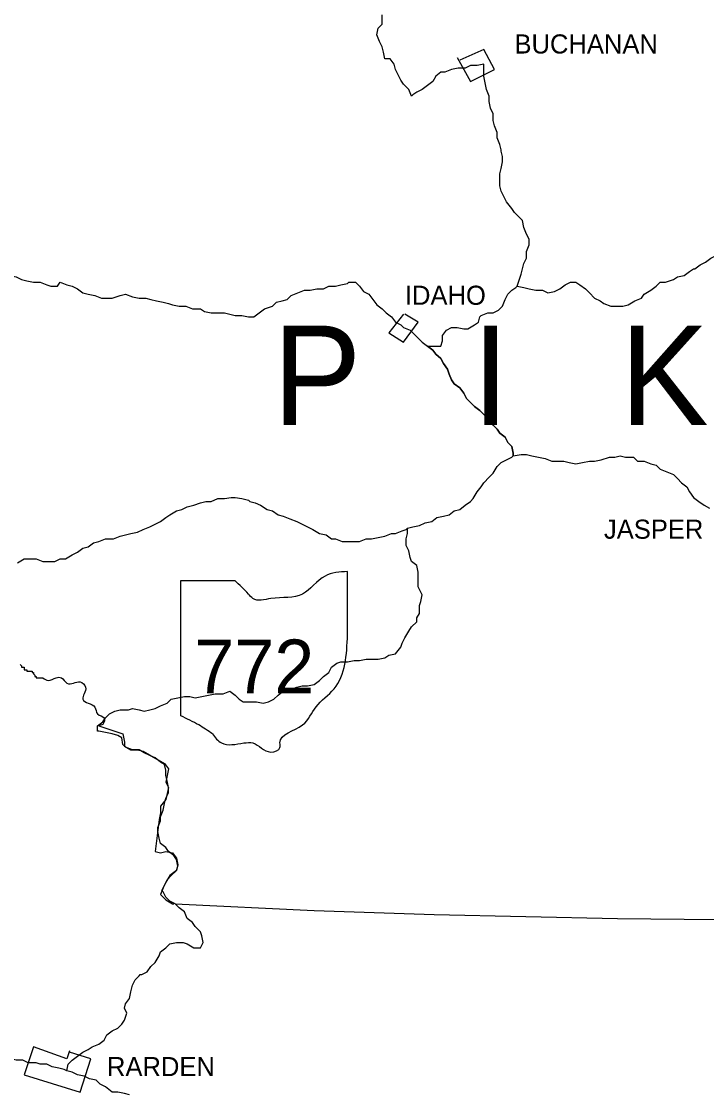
# Model space of a CAD drawing. Extents: x 0 to 34, y 0 to 22.
# Drawn here: x 5.139 to 5.838, y 17.195 to 18.289 of the extents above; entities that cross this region are included whole.
import ezdxf

# ---------------------------------------------------------------- set-up
doc = ezdxf.new("R2010")
doc.units = 0
doc.layers.add('Default', color=7, linetype='Continuous')
doc.layers.add('TR_Turning_Path1', color=7, linetype='Continuous')

msp = doc.modelspace()

# ---------------------------------------------------------------- linework, layer by layer
at = {"layer": 'Default'}
msp.add_line((5.2224, 17.5717), (5.2183, 17.5703), dxfattribs=at)
for points in [[(5.5373, 18.2125), (5.5346, 18.2193), (5.5291, 18.2247), (5.5264, 18.2288), (5.5237, 18.2343), (5.521, 18.2397), (5.5196, 18.2452), (5.5155, 18.2506), (5.51, 18.2506), (5.5087, 18.2575), (5.5073, 18.2629), (5.5046, 18.2684), (5.5019, 18.2752), (5.5032, 18.282), (5.5073, 18.2861), (5.5073, 18.2929), (5.5073, 18.2956)], [(5.5837, 18.252), (5.5973, 18.2275), (5.6218, 18.2397), (5.6109, 18.2602), (5.5864, 18.2493)], [(5.6109, 18.2452), (5.6041, 18.2438), (5.5973, 18.2438), (5.5919, 18.2411), (5.585, 18.2411), (5.5782, 18.2397), (5.5714, 18.237), (5.5673, 18.237), (5.5619, 18.2329), (5.5591, 18.2275), (5.5537, 18.2234), (5.5482, 18.2193), (5.5428, 18.2166), (5.5387, 18.2138), (5.5373, 18.2125)], [(5.6287, 18.1579), (5.6273, 18.1634), (5.6246, 18.1702), (5.6246, 18.1757), (5.6218, 18.1825), (5.6205, 18.1879), (5.6205, 18.1947), (5.6178, 18.2002), (5.6164, 18.207), (5.6164, 18.2125), (5.6137, 18.2193), (5.6123, 18.2261), (5.6109, 18.2329), (5.6109, 18.237), (5.6109, 18.2438), (5.6109, 18.2452)], [(5.645, 18.0189), (5.6464, 18.0229), (5.6491, 18.0311), (5.6505, 18.0366), (5.6518, 18.042), (5.6546, 18.0475), (5.6546, 18.0543), (5.6573, 18.0611), (5.6573, 18.0666), (5.6546, 18.072), (5.6518, 18.0788), (5.6505, 18.0857), (5.6464, 18.0898), (5.6423, 18.0938), (5.6396, 18.0979), (5.6341, 18.1048), (5.6314, 18.1102), (5.6287, 18.1157), (5.6273, 18.1211), (5.6273, 18.1266), (5.6273, 18.1334), (5.6287, 18.1388), (5.63, 18.1457), (5.63, 18.1511), (5.6287, 18.1566), (5.6287, 18.1566), (5.6287, 18.1579)], [(5.8264, 18.0366), (5.8318, 18.0407), (5.8373, 18.0434), (5.8427, 18.0475), (5.8482, 18.0502), (5.8536, 18.0516), (5.8604, 18.0516), (5.8659, 18.0516), (5.8714, 18.0489), (5.8782, 18.0475), (5.8836, 18.0489), (5.8864, 18.0502)], [(5.056, 17.9957), (5.0628, 17.9957), (5.0669, 17.9998), (5.071, 18.0039), (5.0778, 18.0066), (5.0819, 18.012), (5.0874, 18.0161), (5.0928, 18.0202), (5.0969, 18.0243), (5.101, 18.0284), (5.1078, 18.0311), (5.1133, 18.0325), (5.1201, 18.0311), (5.1269, 18.0298), (5.1337, 18.0284), (5.1392, 18.0257), (5.1447, 18.0243), (5.1515, 18.0229), (5.1583, 18.0229), (5.1651, 18.0202), (5.1692, 18.0189), (5.176, 18.0189), (5.176, 18.0189)], [(5.645, 18.0189), (5.6518, 18.0175), (5.6573, 18.0161), (5.6641, 18.0148), (5.6709, 18.0148), (5.6764, 18.012), (5.6832, 18.0134), (5.6887, 18.0161), (5.6941, 18.0202), (5.6996, 18.0229), (5.705, 18.0229), (5.7091, 18.0202), (5.7146, 18.0161), (5.7187, 18.012), (5.7241, 18.0066), (5.7296, 18.0039), (5.7336, 18.0011), (5.7405, 17.9984), (5.7473, 17.9984), (5.7527, 17.9984), (5.7582, 17.9998), (5.765, 18.0039), (5.7718, 18.0066), (5.7746, 18.0107), (5.7814, 18.0148), (5.7868, 18.0189), (5.7909, 18.0229), (5.7964, 18.0229), (5.8045, 18.0257), (5.8086, 18.0284), (5.8155, 18.0298), (5.8209, 18.0339), (5.825, 18.0366), (5.8264, 18.0366), (5.8264, 18.0366)], [(5.176, 18.0189), (5.1787, 18.0229), (5.1856, 18.0202), (5.191, 18.0189), (5.1965, 18.0161), (5.2019, 18.012), (5.2074, 18.0107), (5.2142, 18.0093), (5.221, 18.0066), (5.2265, 18.0066), (5.2319, 18.0066), (5.2401, 18.0093), (5.2455, 18.0107), (5.2524, 18.0079), (5.2592, 18.0066), (5.266, 18.0066), (5.2714, 18.0052), (5.2769, 18.0039), (5.2837, 18.0025), (5.2892, 18.0011), (5.2933, 17.9998), (5.2933, 17.9998)], [(5.2933, 17.9998), (5.3001, 17.9984), (5.3069, 17.9984), (5.3137, 17.9957), (5.3219, 17.9957), (5.326, 17.993), (5.3328, 17.9916), (5.3396, 17.9916), (5.3464, 17.9916), (5.3519, 17.9902), (5.3573, 17.9889), (5.3642, 17.9889), (5.371, 17.9875), (5.3764, 17.9875), (5.3819, 17.9916), (5.3873, 17.9957), (5.3955, 17.9984), (5.3996, 18.0025), (5.4051, 18.0039), (5.4105, 18.0052), (5.4146, 18.0093), (5.4214, 18.012), (5.4282, 18.0148), (5.4337, 18.0148), (5.4405, 18.0161), (5.4473, 18.0161), (5.4528, 18.0189), (5.4596, 18.0189), (5.4651, 18.0202), (5.4719, 18.0216), (5.4732, 18.0229)], [(5.4732, 18.0229), (5.4801, 18.0229), (5.4841, 18.0189), (5.4882, 18.0134), (5.4937, 18.0107), (5.4978, 18.0052), (5.5019, 17.9998), (5.5073, 17.9957), (5.5114, 17.9916), (5.5169, 17.9875), (5.521, 17.982), (5.5264, 17.9793), (5.5291, 17.9766), (5.536, 17.9739), (5.5387, 17.9711), (5.5441, 17.9657), (5.5482, 17.9616), (5.5537, 17.9575), (5.5537, 17.9575), (5.5537, 17.9575)], [(5.6082, 17.9889), (5.615, 17.9916), (5.6205, 17.9916), (5.6259, 17.9943), (5.63, 17.9984), (5.6328, 18.0052), (5.6355, 18.0107), (5.6396, 18.0148), (5.6437, 18.0175), (5.645, 18.0189)], [(5.5291, 17.9902), (5.5141, 17.9711), (5.5291, 17.9616), (5.5441, 17.982), (5.5305, 17.9902)], [(5.5537, 17.9575), (5.5605, 17.9575), (5.5673, 17.9575), (5.5687, 17.963), (5.5687, 17.9684), (5.5728, 17.9739), (5.5782, 17.9766), (5.5837, 17.9766), (5.5905, 17.9752), (5.5946, 17.9752), (5.6014, 17.9793), (5.6055, 17.982), (5.6069, 17.9875), (5.6069, 17.9875), (5.6082, 17.9889)], [(5.6409, 17.8457), (5.6409, 17.8471), (5.6409, 17.8484), (5.6396, 17.8552), (5.6355, 17.8593), (5.6328, 17.8648), (5.6273, 17.8689), (5.6246, 17.873), (5.6205, 17.8771), (5.6164, 17.8825), (5.6109, 17.888), (5.6069, 17.8921), (5.6014, 17.8961), (5.5973, 17.9002), (5.5932, 17.9043), (5.5905, 17.9098), (5.5864, 17.9152), (5.5809, 17.9193), (5.5782, 17.9234), (5.5755, 17.9289), (5.5741, 17.9343), (5.57, 17.9398), (5.5673, 17.9452), (5.5619, 17.9493), (5.5591, 17.9534), (5.5537, 17.9575)], [(5.5537, 17.9575), (5.5591, 17.9534), (5.5619, 17.9493), (5.5673, 17.9452), (5.57, 17.9398), (5.5741, 17.9343), (5.5755, 17.9289), (5.5782, 17.9234), (5.5809, 17.9193), (5.5864, 17.9152), (5.5905, 17.9098), (5.5932, 17.9043), (5.5973, 17.9002), (5.6014, 17.8961), (5.6069, 17.8921), (5.6109, 17.888), (5.6164, 17.8825), (5.6205, 17.8771), (5.6246, 17.873), (5.6273, 17.8689), (5.6328, 17.8648), (5.6355, 17.8593), (5.6396, 17.8552), (5.6409, 17.8484), (5.6409, 17.8471), (5.6409, 17.8457)], [(5.5332, 17.7721), (5.5387, 17.7734), (5.5455, 17.7748), (5.551, 17.7775), (5.5578, 17.7789), (5.5632, 17.783), (5.57, 17.7843), (5.5755, 17.7857), (5.5809, 17.7898), (5.5864, 17.7912), (5.5919, 17.7953), (5.5973, 17.7993), (5.6, 17.8021), (5.6041, 17.8089), (5.6082, 17.8143), (5.6109, 17.8184), (5.6164, 17.8239), (5.6205, 17.828), (5.6246, 17.8348), (5.6287, 17.8389), (5.6341, 17.8416), (5.6396, 17.8443), (5.6409, 17.8457), (5.6409, 17.8457)], [(5.5332, 17.7721), (5.5387, 17.7734), (5.5455, 17.7748), (5.551, 17.7775), (5.5578, 17.7789), (5.5632, 17.783), (5.57, 17.7843), (5.5755, 17.7857), (5.5809, 17.7898), (5.5864, 17.7912), (5.5919, 17.7953), (5.5973, 17.7993), (5.6, 17.8021), (5.6041, 17.8089), (5.6082, 17.8143), (5.6109, 17.8184), (5.6164, 17.8239), (5.6205, 17.828), (5.6246, 17.8348), (5.6287, 17.8389), (5.6341, 17.8416), (5.6396, 17.8443), (5.6409, 17.8457), (5.6409, 17.8457)], [(5.6409, 17.8457), (5.6491, 17.8471), (5.6546, 17.8471), (5.66, 17.8457), (5.6668, 17.8443), (5.6737, 17.843), (5.6805, 17.8402), (5.6859, 17.8402), (5.6927, 17.8402), (5.6982, 17.8389), (5.705, 17.8375), (5.7118, 17.8389), (5.7187, 17.8402), (5.7241, 17.8402), (5.7309, 17.8416), (5.7391, 17.8443), (5.7446, 17.8443), (5.75, 17.8457), (5.7555, 17.8443), (5.7636, 17.8443), (5.7677, 17.8402), (5.7746, 17.8402), (5.7814, 17.8375), (5.7868, 17.8362), (5.7909, 17.8321), (5.7977, 17.8293), (5.8045, 17.8266), (5.8086, 17.8225), (5.8127, 17.8184), (5.8182, 17.8143), (5.8209, 17.8089), (5.825, 17.8034), (5.8305, 17.7993), (5.8359, 17.7953), (5.8414, 17.7925)], [(5.6409, 17.8457), (5.6491, 17.8471), (5.6546, 17.8471), (5.66, 17.8457), (5.6668, 17.8443), (5.6737, 17.843), (5.6805, 17.8402), (5.6859, 17.8402), (5.6927, 17.8402), (5.6982, 17.8389), (5.705, 17.8375), (5.7118, 17.8389), (5.7187, 17.8402), (5.7241, 17.8402), (5.7309, 17.8416), (5.7391, 17.8443), (5.7446, 17.8443), (5.75, 17.8457), (5.7555, 17.8443), (5.7636, 17.8443), (5.7677, 17.8402), (5.7746, 17.8402), (5.7814, 17.8375), (5.7868, 17.8362), (5.7909, 17.8321), (5.7977, 17.8293), (5.8045, 17.8266), (5.8086, 17.8225), (5.8127, 17.8184), (5.8182, 17.8143), (5.8209, 17.8089), (5.825, 17.8034), (5.8305, 17.7993), (5.8359, 17.7953), (5.8414, 17.7925)], [(5.2265, 17.7612), (5.2333, 17.7612), (5.2401, 17.7639), (5.2455, 17.7653), (5.251, 17.7666), (5.2578, 17.768), (5.2633, 17.7707), (5.2701, 17.7734), (5.2755, 17.7762), (5.281, 17.7789), (5.2864, 17.783), (5.2905, 17.7857), (5.2974, 17.7898), (5.3028, 17.7912), (5.3083, 17.7939), (5.3151, 17.7953), (5.3219, 17.798), (5.3273, 17.7993), (5.3328, 17.7993), (5.3396, 17.8021), (5.3464, 17.8021), (5.3533, 17.8034), (5.3573, 17.8034), (5.3642, 17.8021), (5.371, 17.8007), (5.3723, 17.7993), (5.3723, 17.7993)], [(5.3723, 17.7993), (5.3778, 17.798), (5.3832, 17.7953), (5.3901, 17.7912), (5.3955, 17.7898), (5.401, 17.7857), (5.4064, 17.7843), (5.4132, 17.7816), (5.4201, 17.7789), (5.4255, 17.7762), (5.431, 17.7734), (5.4364, 17.7707), (5.4432, 17.7666), (5.4501, 17.7653), (5.4555, 17.7612), (5.4596, 17.7612), (5.4664, 17.7584), (5.4719, 17.7584), (5.4787, 17.7584), (5.4841, 17.7584), (5.491, 17.7612), (5.4964, 17.7612), (5.5032, 17.7625), (5.51, 17.7639), (5.5169, 17.7666), (5.521, 17.7666), (5.5278, 17.7694), (5.5319, 17.7707), (5.5332, 17.7721)], [(5.5428, 17.6807), (5.5455, 17.6848), (5.5455, 17.693), (5.5469, 17.6971), (5.5482, 17.7039), (5.5455, 17.7094), (5.5441, 17.7121), (5.5441, 17.7203), (5.5441, 17.7271), (5.5428, 17.7339), (5.5373, 17.738), (5.536, 17.7421), (5.5346, 17.7489), (5.5319, 17.7544), (5.5319, 17.7612), (5.5332, 17.7666), (5.5332, 17.7707), (5.5332, 17.7721)], [(5.1351, 17.7366), (5.1419, 17.7407), (5.1474, 17.7407), (5.1542, 17.7407), (5.161, 17.738), (5.1665, 17.738), (5.1733, 17.738), (5.1787, 17.7407), (5.1842, 17.7407), (5.191, 17.7448), (5.1965, 17.7475), (5.2019, 17.7516), (5.2074, 17.753), (5.2128, 17.7571), (5.2183, 17.7584), (5.2251, 17.7612), (5.2265, 17.7612), (5.2265, 17.7612)], [(5.472, 17.6633), (5.472, 17.7278)], [(5.3018, 17.5805), (5.3018, 17.7186), (5.357, 17.7186)], [(5.4841, 17.6371), (5.491, 17.6385), (5.4964, 17.6385), (5.5032, 17.6385), (5.51, 17.6398), (5.5141, 17.6426), (5.521, 17.6439), (5.5264, 17.6507), (5.5278, 17.6548), (5.5305, 17.6603), (5.5346, 17.6671), (5.5373, 17.6712), (5.5428, 17.6766), (5.5428, 17.6794), (5.5428, 17.6807)], [(5.1378, 17.633), (5.1392, 17.6316), (5.1392, 17.6316), (5.1392, 17.6316), (5.1392, 17.6316), (5.1392, 17.6316), (5.1392, 17.6316), (5.1392, 17.6303), (5.1392, 17.6303), (5.1392, 17.6303), (5.1392, 17.6303), (5.1406, 17.6303), (5.1406, 17.6303), (5.1419, 17.6303), (5.1419, 17.6303), (5.1419, 17.6303), (5.1419, 17.6303), (5.1419, 17.6303), (5.1419, 17.6289), (5.1419, 17.6289), (5.1419, 17.6276), (5.1433, 17.6276), (5.1433, 17.6276), (5.1433, 17.6276), (5.1433, 17.6276), (5.1447, 17.6276), (5.1447, 17.6276), (5.1447, 17.6262), (5.1447, 17.6262), (5.146, 17.6262), (5.146, 17.6262), (5.146, 17.6262), (5.146, 17.6262), (5.1474, 17.6262), (5.1474, 17.6262), (5.1487, 17.6262), (5.1487, 17.6262), (5.1487, 17.6262), (5.1487, 17.6262), (5.1501, 17.6262), (5.1501, 17.6262), (5.1501, 17.6262), (5.1501, 17.6262), (5.1501, 17.6262), (5.1501, 17.6248), (5.1501, 17.6248), (5.1515, 17.6248), (5.1515, 17.6248), (5.1515, 17.6235), (5.1515, 17.6235), (5.1515, 17.6235), (5.1515, 17.6235), (5.1515, 17.6235), (5.1515, 17.6235), (5.1515, 17.6235), (5.1515, 17.6235), (5.1528, 17.6221), (5.1528, 17.6221), (5.1528, 17.6221), (5.1528, 17.6221), (5.1528, 17.6221), (5.1528, 17.6207), (5.1542, 17.6207), (5.1542, 17.6194), (5.1556, 17.6194), (5.1556, 17.6194), (5.1556, 17.6194), (5.1556, 17.6194), (5.1556, 17.6194), (5.1556, 17.6194), (5.1556, 17.6194), (5.1556, 17.6194), (5.1569, 17.6194), (5.1583, 17.6194), (5.1583, 17.6194)], [(5.3451, 17.603), (5.3519, 17.6057), (5.3573, 17.6017), (5.3614, 17.5976), (5.3655, 17.5948), (5.3723, 17.5948), (5.3792, 17.5948), (5.386, 17.5935), (5.3914, 17.5948), (5.3969, 17.5976), (5.401, 17.6017), (5.4064, 17.6057), (5.4132, 17.6071), (5.4201, 17.6098), (5.4255, 17.6112), (5.431, 17.6112), (5.4378, 17.6126), (5.4432, 17.6166), (5.4473, 17.6207), (5.4528, 17.6248), (5.4555, 17.6303), (5.461, 17.6344), (5.4651, 17.6357), (5.4719, 17.6357), (5.4787, 17.6371), (5.4828, 17.6371), (5.4841, 17.6371)], [(5.1583, 17.6194), (5.1583, 17.6194), (5.1583, 17.6194), (5.1583, 17.6194), (5.1583, 17.6194), (5.1583, 17.6194), (5.1596, 17.6194), (5.1596, 17.6194), (5.1596, 17.6194), (5.1596, 17.6194), (5.1596, 17.6194), (5.1596, 17.6194), (5.1596, 17.6194), (5.161, 17.6194), (5.161, 17.6194), (5.161, 17.6194), (5.161, 17.6194)], [(5.2251, 17.5785), (5.2292, 17.5826), (5.2346, 17.5853), (5.2401, 17.5867), (5.2483, 17.5867), (5.2524, 17.588), (5.2592, 17.5867), (5.2646, 17.5853), (5.2701, 17.5867), (5.2755, 17.588), (5.281, 17.5907), (5.2878, 17.5935), (5.2919, 17.5976), (5.2987, 17.5989), (5.3055, 17.6003), (5.311, 17.6003), (5.3164, 17.5989), (5.3233, 17.6003), (5.3301, 17.6017), (5.3369, 17.603), (5.3437, 17.603), (5.3451, 17.603)], [(5.2169, 17.5648), (5.2169, 17.5703), (5.2224, 17.5744), (5.2251, 17.5785)], [(5.281, 17.4776), (5.2837, 17.4844), (5.2851, 17.4912), (5.2864, 17.4967), (5.2892, 17.5021), (5.2892, 17.5076), (5.2878, 17.5144), (5.2864, 17.5198), (5.2864, 17.5253), (5.2851, 17.5308), (5.281, 17.5335), (5.2755, 17.5376), (5.2701, 17.5403), (5.2646, 17.543), (5.2592, 17.5458), (5.2524, 17.5458), (5.2455, 17.5485), (5.2428, 17.5512), (5.2415, 17.558), (5.2374, 17.5607), (5.2319, 17.5621), (5.2251, 17.5635), (5.2183, 17.5648), (5.2169, 17.5648), (5.2169, 17.5648)], [(5.2183, 17.5703), (5.2428, 17.5621), (5.2442, 17.5539), (5.2442, 17.5498), (5.251, 17.5458), (5.2578, 17.5458), (5.2633, 17.5444), (5.2851, 17.5321), (5.2892, 17.5267), (5.2878, 17.5198), (5.2864, 17.513), (5.2892, 17.5076), (5.2864, 17.4953), (5.281, 17.4885), (5.281, 17.4817), (5.2796, 17.4749), (5.2755, 17.4421), (5.281, 17.4408), (5.2864, 17.4421), (5.2933, 17.4408), (5.2974, 17.4353), (5.2987, 17.4285), (5.2974, 17.423), (5.2905, 17.4176), (5.2864, 17.4108), (5.2837, 17.4053), (5.281, 17.3985), (5.2864, 17.393), (5.2933, 17.389), (5.2946, 17.389)], [(5.2824, 17.4026), (5.2851, 17.408), (5.2878, 17.4135), (5.2919, 17.4176), (5.2974, 17.423), (5.2987, 17.4271), (5.2974, 17.4339), (5.2946, 17.438), (5.2892, 17.4421), (5.2864, 17.4462), (5.281, 17.4503), (5.2796, 17.4558), (5.2783, 17.4626), (5.2783, 17.4667), (5.281, 17.4735), (5.281, 17.4776), (5.281, 17.4776)], [(5.2619, 17.3167), (5.2674, 17.3194), (5.2714, 17.3249), (5.2755, 17.329), (5.2796, 17.3358), (5.281, 17.3399), (5.2864, 17.344), (5.2905, 17.3481), (5.2974, 17.3494), (5.3042, 17.3494), (5.3083, 17.3481), (5.3151, 17.344), (5.3219, 17.344), (5.3246, 17.3494), (5.3233, 17.3562), (5.3219, 17.3603), (5.3164, 17.3658), (5.3137, 17.3699), (5.3083, 17.374), (5.3055, 17.3808), (5.3001, 17.3849), (5.296, 17.389), (5.2905, 17.3917), (5.2864, 17.3958), (5.2837, 17.4012), (5.2837, 17.4012), (5.2824, 17.4026)], [(5.296, 17.389), (5.4378, 17.3821), (5.5605, 17.378), (5.7473, 17.374), (5.8836, 17.3726), (5.9518, 17.3699), (6.1413, 17.3617), (6.4194, 17.3467), (6.5299, 17.3399), (6.6894, 17.329), (6.7235, 17.3262)], [(5.1856, 17.2185), (5.1869, 17.2253), (5.191, 17.2294), (5.1965, 17.2335), (5.2019, 17.2376), (5.2074, 17.2403), (5.2115, 17.2431), (5.2183, 17.2458), (5.2237, 17.2499), (5.2265, 17.2553), (5.2319, 17.2594), (5.2374, 17.2622), (5.2415, 17.2662), (5.2442, 17.2703), (5.2469, 17.2772), (5.2442, 17.2826), (5.2455, 17.2867), (5.2496, 17.2922), (5.251, 17.299), (5.2524, 17.3058), (5.2551, 17.3112), (5.2592, 17.3153), (5.2605, 17.3167), (5.2619, 17.3167)], [(5.1856, 17.2185), (5.1828, 17.2199), (5.1774, 17.2213), (5.1706, 17.2226), (5.1651, 17.2253), (5.1583, 17.2253), (5.1542, 17.2267), (5.146, 17.2267), (5.1406, 17.2294), (5.1337, 17.2294), (5.1283, 17.2308), (5.1201, 17.2335), (5.116, 17.2363), (5.1119, 17.2403), (5.1065, 17.2431), (5.1024, 17.2499), (5.0969, 17.2526), (5.0901, 17.254)], [(5.1883, 17.239), (5.1856, 17.2308), (5.1515, 17.2431), (5.1419, 17.2144), (5.1992, 17.1967), (5.2101, 17.2308), (5.1883, 17.2376)], [(5.2496, 17.194), (5.2442, 17.1954), (5.2374, 17.1967), (5.2319, 17.1967), (5.2251, 17.2022), (5.2196, 17.2049), (5.2155, 17.209), (5.2087, 17.2103), (5.2033, 17.2131), (5.1965, 17.2144), (5.191, 17.2172), (5.1856, 17.2185)]]:
    msp.add_lwpolyline(points, dxfattribs=at)
for points in [[(5.472, 17.7278), (5.449, 17.7232), (5.426, 17.7048), (5.3938, 17.7002), (5.3754, 17.7002), (5.3708, 17.7048), (5.357, 17.7186)], [(5.334, 17.5621), (5.3432, 17.5529), (5.3662, 17.5529), (5.3754, 17.5529), (5.3938, 17.5437), (5.403, 17.5483), (5.403, 17.5529), (5.426, 17.5713), (5.4398, 17.5897), (5.4582, 17.6081), (5.472, 17.6633)], [(5.161, 17.6194), (5.1665, 17.6166), (5.1746, 17.6194), (5.1801, 17.6194), (5.1856, 17.6139), (5.1924, 17.6139), (5.1992, 17.6153), (5.2046, 17.6098), (5.2033, 17.603), (5.2019, 17.5976), (5.2074, 17.5935), (5.2142, 17.5894), (5.2169, 17.5826), (5.2237, 17.5785), (5.2224, 17.5717)], [(5.334, 17.5621), (5.3202, 17.5713), (5.3018, 17.5805)]]:
    msp.add_spline(points, degree=3, dxfattribs=at)

# ---------------------------------------------------------------- texts
for s, height, p in [('BUCHANAN', 0.0195, (5.6423, 18.2561)), ('IDAHO', 0.0195, (5.5305, 17.9998)), ('JASPER', 0.0195, (5.7336, 17.7612)), ('772', 0.05486, (5.3156, 17.6035)), ('RARDEN', 0.0195, (5.2265, 17.2131))]:
    msp.add_text(s, height=height, dxfattribs=at).set_placement(p)
at = {"layer": 'TR_Turning_Path1'}
msp.add_text('P   I   K   E', height=0.101489, dxfattribs=at).set_placement((5.3955, 17.8771))

doc.saveas('drawing.dxf')
